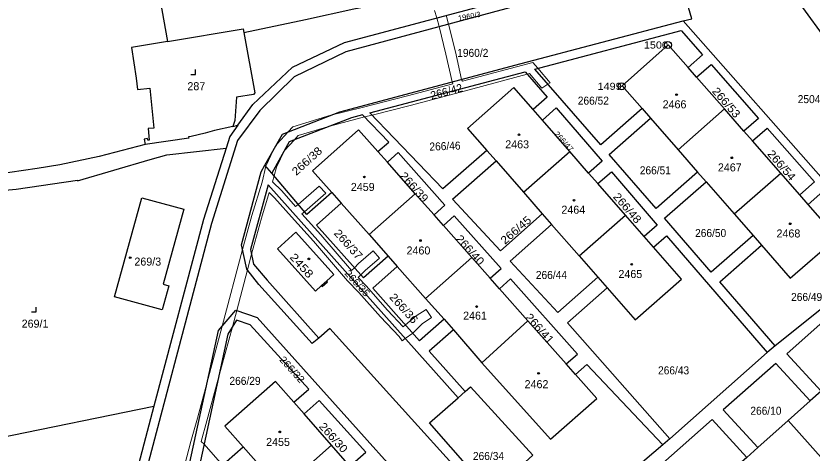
# Model space of a CAD drawing. Extents: x -679733 to -673243, y -1075091 to -1066557.
# Drawn here: x -676434.7 to -676265.6, y -1072010.9 to -1071918.1 of the extents above; entities that cross this region are included whole.
import ezdxf
from ezdxf.enums import TextEntityAlignment as Align

# ---------------------------------------------------------------- set-up
doc = ezdxf.new("R2010")
doc.units = 0
doc.header["$LTSCALE"] = 0.68
for name, color, linetype, lineweight in [('1', 7, 'Continuous', 25), ('13', 7, 'Continuous', 13), ('3', 7, 'Continuous', 25), ('4', 7, 'Continuous', 13), ('5', 7, 'Continuous', 25), ('8', 7, 'Continuous', 25)]:
    doc.layers.add(name, color=color, linetype=linetype, lineweight=lineweight)
doc.layers.add('2', color=7, linetype='Continuous')

msp = doc.modelspace()

# ---------------------------------------------------------------- linework, layer by layer
at = {"layer": '1'}
for p, q in [((-676261.1, -1071955.35), (-676292.99, -1071919.16)), ((-676290.15, -1071931.15), (-676291.95, -1071929.1)), ((-676322.91, -1071940.27), (-676324.88, -1071938.01)), ((-676359.72, -1071964.55), (-676349.94, -1071955.87)), ((-676301.3, -1071964.97), (-676305.24, -1071960.46)), ((-676339.34, -1071997.87), (-676340.79, -1071999.21)), ((-676446.81, -1072009.39), (-676405.43, -1072000.99))]:
    msp.add_line(p, q, dxfattribs=at)
for points in [[(-676408.69, -1071881.95), (-676408.31, -1071891.09), (-676404.9, -1071910.06), (-676402.54, -1071923.54)], [(-676386.32, -1071921.67), (-676373.19, -1071918.89), (-676362.98, -1071916.66), (-676353.15, -1071914.69), (-676349.6, -1071914.02), (-676331.48, -1071909.81), (-676326.61, -1071908.65), (-676299.34, -1071899.31), (-676297.85, -1071896.38)], [(-676387.58, -1071941.35), (-676384.43, -1071936.96), (-676375.96, -1071928.98), (-676364.91, -1071923.77), (-676304.78, -1071907.71), (-676297.93, -1071904.43), (-676296.28, -1071899.99)], [(-676295.13, -1071902.52), (-676296.41, -1071905.95), (-676304.35, -1071909.5), (-676364.66, -1071925.74), (-676375.64, -1071931.09), (-676382.94, -1071938.2), (-676387.67, -1071944.57), (-676393.17, -1071962.19), (-676409.55, -1072024.04), (-676425.12, -1072082.52), (-676427.14, -1072091.8), (-676426.89, -1072108.9), (-676422.15, -1072126.21), (-676412.96, -1072141.55), (-676403.18, -1072152.89), (-676393.86, -1072163.85), (-676389.15, -1072169.1)], [(-676292.99, -1071919.16), (-676291.15, -1071918.74), (-676292.61, -1071913.87), (-676290.05, -1071912.25)], [(-676269.62, -1071912.9), (-676269.95, -1071913.15), (-676260.68, -1071925.96), (-676251.05, -1071935.29), (-676244.6, -1071929.19)], [(-676381.82, -1071949.81), (-676378.12, -1071943.23), (-676365.91, -1071938.49), (-676327.4, -1071928.26), (-676292.99, -1071919.16)], [(-676402.54, -1071923.54), (-676386.46, -1071920.91), (-676386.32, -1071921.67)], [(-676386.32, -1071921.67), (-676384.01, -1071934.48), (-676384.27, -1071934.79), (-676387.85, -1071935.36), (-676387.91, -1071936.4), (-676388.24, -1071940.31), (-676388.68, -1071941.6), (-676387.58, -1071941.35)], [(-676301.74, -1071937.8), (-676310.53, -1071945.49), (-676324.5, -1071929.42), (-676293.47, -1071921.21), (-676288.89, -1071926.41), (-676291.95, -1071929.1)], [(-676402.54, -1071923.54), (-676410.14, -1071924.87), (-676409.17, -1071931.32), (-676408.91, -1071933.75), (-676406.28, -1071933.5), (-676405.46, -1071941.95), (-676406.64, -1071942.06), (-676406.4, -1071944.48), (-676406.69, -1071944.52), (-676406.74, -1071944.17), (-676407.46, -1071944.28), (-676407.29, -1071945.44)], [(-676291.95, -1071929.1), (-676296.21, -1071924.24), (-676305.98, -1071932.95), (-676301.74, -1071937.8), (-676299.95, -1071939.84), (-676294.07, -1071946.56), (-676284.24, -1071937.88), (-676290.15, -1071931.15)], [(-676290.15, -1071931.15), (-676287.09, -1071928.46), (-676277.01, -1071939.9), (-676280.1, -1071942.61)], [(-676334.72, -1071946.67), (-676344.04, -1071954.84), (-676359.52, -1071938.68), (-676326.6, -1071929.97), (-676321.9, -1071935.41), (-676324.88, -1071938.01)], [(-676324.88, -1071938.01), (-676328.95, -1071933.36), (-676338.79, -1071942.02), (-676334.72, -1071946.67), (-676332.75, -1071948.92), (-676326.93, -1071955.55), (-676317.1, -1071946.91), (-676322.91, -1071940.27)], [(-676357.83, -1071946.94), (-676355.54, -1071944.92), (-676361.11, -1071939.11), (-676363.48, -1071939.75), (-676376.69, -1071944.88), (-676380.4, -1071951.48)], [(-676322.91, -1071940.27), (-676319.95, -1071937.68), (-676310.2, -1071948.96), (-676313.09, -1071951.49)], [(-676294.07, -1071946.56), (-676289.95, -1071951.28), (-676288.16, -1071953.33), (-676282.18, -1071960.17), (-676272.29, -1071951.51), (-676278.3, -1071944.66), (-676280.1, -1071942.61), (-676284.24, -1071937.88)], [(-676289.95, -1071951.28), (-676298.78, -1071959.01), (-676308.75, -1071947.54), (-676299.95, -1071939.84)], [(-676388.68, -1071941.6), (-676392.51, -1071942.48), (-676394.55, -1071943.02), (-676397.5, -1071943.7), (-676398.07, -1071943.8), (-676398.02, -1071944.08), (-676407.29, -1071945.44)], [(-676387.58, -1071941.35), (-676389.28, -1071943.71), (-676390.08, -1071946.22)], [(-676357.83, -1071946.94), (-676361.97, -1071942.33), (-676371.74, -1071951), (-676367.63, -1071955.64), (-676365.63, -1071957.88), (-676359.72, -1071964.55)], [(-676278.3, -1071944.66), (-676275.2, -1071941.94), (-676265.12, -1071953.38), (-676268.24, -1071956.12)], [(-676407.29, -1071945.44), (-676417.02, -1071948.01), (-676425.37, -1071949.72), (-676430.22, -1071950.53), (-676436.03, -1071951.34), (-676444.6, -1071952.15), (-676451.96, -1071952.38), (-676459.08, -1071952.16), (-676466.06, -1071951.13)], [(-676446.81, -1072009.39), (-676450.6, -1071997.32), (-676455.21, -1071989.93), (-676455.68, -1071988.73), (-676463.71, -1071957.6), (-676434.64, -1071954.92), (-676421.63, -1071953.01), (-676421.61, -1071953.11), (-676406.22, -1071948.58), (-676402.7, -1071947.59), (-676390.08, -1071946.22)], [(-676390.08, -1071946.22), (-676394.9, -1071961.33), (-676405.43, -1072000.99), (-676410.13, -1072018.72)], [(-676349.94, -1071955.87), (-676355.83, -1071949.19), (-676357.83, -1071946.94)], [(-676345.91, -1071960.37), (-676343.6, -1071958.32), (-676353.55, -1071947.16), (-676355.83, -1071949.19)], [(-676311.12, -1071953.74), (-676313.09, -1071951.49), (-676317.1, -1071946.91)], [(-676322.93, -1071960.12), (-676331.81, -1071968), (-676342.01, -1071957.03), (-676332.75, -1071948.92)], [(-676370.36, -1071986.54), (-676371.83, -1071987.69), (-676383.12, -1071975.15), (-676385.67, -1071971.87), (-676386.84, -1071966.72), (-676382.61, -1071951.21), (-676381.82, -1071949.81)], [(-676367.63, -1071955.64), (-676372.9, -1071960.32), (-676380.4, -1071951.48), (-676381.82, -1071949.81)], [(-676311.12, -1071953.74), (-676308.25, -1071951.23), (-676298.5, -1071962.52), (-676301.3, -1071964.97)], [(-676276.37, -1071966.81), (-676270.27, -1071973.78), (-676260.32, -1071965.15), (-676266.45, -1071958.17), (-676268.24, -1071956.12), (-676272.29, -1071951.51)], [(-676340.79, -1071999.21), (-676381.18, -1071953.99), (-676384.92, -1071967.69), (-676384.28, -1071970.84), (-676381.34, -1071974.24), (-676370.36, -1071986.54)], [(-676326.93, -1071955.55), (-676322.93, -1071960.12), (-676320.95, -1071962.38), (-676315.07, -1071969.09), (-676305.24, -1071960.46), (-676311.12, -1071953.74)], [(-676278.15, -1071964.77), (-676287.04, -1071972.53), (-676297, -1071961.06), (-676288.16, -1071953.33)], [(-676347.71, -1071978.09), (-676337.92, -1071969.41), (-676343.92, -1071962.62), (-676345.91, -1071960.37), (-676349.94, -1071955.87)], [(-676266.45, -1071958.17), (-676263.32, -1071955.43), (-676262.41, -1071956.46), (-676261.1, -1071955.35)], [(-676355.68, -1071969.11), (-676360.9, -1071973.74), (-676370.9, -1071962.56), (-676365.63, -1071957.88)], [(-676334, -1071973.8), (-676331.66, -1071971.72), (-676341.61, -1071960.56), (-676343.92, -1071962.62)], [(-676282.18, -1071960.17), (-676278.15, -1071964.77), (-676276.37, -1071966.81)], [(-676311.13, -1071973.59), (-676319.63, -1071981.09), (-676329.78, -1071970.18), (-676320.95, -1071962.38)], [(-676359.72, -1071964.55), (-676355.68, -1071969.11), (-676353.72, -1071971.31), (-676347.71, -1071978.09)], [(-676309.16, -1071975.83), (-676303.21, -1071982.62), (-676293.39, -1071974.01), (-676299.33, -1071967.22), (-676301.3, -1071964.97)], [(-676299.33, -1071967.22), (-676296.55, -1071964.78), (-676275.14, -1071989.58)], [(-676273.47, -1071988.14), (-676285.25, -1071974.58), (-676276.37, -1071966.81)], [(-676335.74, -1071991.74), (-676325.97, -1071982.85), (-676332.01, -1071976.04), (-676334, -1071973.8), (-676337.92, -1071969.41)], [(-676315.07, -1071969.09), (-676311.13, -1071973.59), (-676309.16, -1071975.83)], [(-676343.8, -1071982.49), (-676348.98, -1071987.09), (-676358.94, -1071975.94), (-676353.72, -1071971.31)], [(-676317.84, -1071992.01), (-676315.45, -1071989.9), (-676329.66, -1071973.96), (-676332.01, -1071976.04)], [(-676295.84, -1072007.9), (-676317.6, -1071983.28), (-676309.16, -1071975.83)], [(-676253.86, -1071979.52), (-676258.66, -1071976.34), (-676273.47, -1071988.14)], [(-676347.71, -1071978.09), (-676343.8, -1071982.49), (-676341.81, -1071984.75), (-676335.74, -1071991.74)], [(-676254.89, -1071980.47), (-676258.79, -1071979.07), (-676271, -1071989.84), (-676263.67, -1071997.76)], [(-676390.45, -1072017.54), (-676393.75, -1072020.45), (-676398.47, -1072016.2), (-676391.69, -1071984.93), (-676388.01, -1071980.59), (-676383.5, -1071982.16), (-676332.46, -1072039.02)], [(-676375.71, -1072000.14), (-676372.54, -1071997.35), (-676384.98, -1071983.69), (-676387.9, -1071982.71), (-676389.69, -1071985.66), (-676395.95, -1072014.53), (-676393.53, -1072015.85), (-676386.44, -1072009.61)], [(-676335.74, -1071991.74), (-676321.17, -1072008), (-676311.37, -1071999.31), (-676315.85, -1071994.26), (-676317.84, -1071992.01), (-676325.97, -1071982.85)], [(-676324.68, -1072032.42), (-676368.06, -1071984.49), (-676370.36, -1071986.54)], [(-676341.81, -1071984.75), (-676346.97, -1071989.33), (-676339.34, -1071997.87)], [(-676273.47, -1071988.14), (-676275.14, -1071989.58), (-676295.84, -1072007.9), (-676297.3, -1072009.2), (-676324.68, -1072032.42)], [(-676297.3, -1072009.2), (-676313.46, -1071992.13), (-676315.85, -1071994.26)], [(-676266.03, -1071999.86), (-676273.36, -1071991.92), (-676284.49, -1072001.73), (-676277.17, -1072009.77)], [(-676375.71, -1072000.14), (-676379.61, -1071995.72), (-676390.34, -1072005.18), (-676386.44, -1072009.61)], [(-676339.34, -1071997.87), (-676338.18, -1071996.86), (-676324.95, -1072011.36), (-676333.76, -1072019.47), (-676346.85, -1072004.49), (-676340.79, -1071999.21)], [(-676263.67, -1071997.76), (-676266.03, -1071999.86), (-676270.68, -1072004)], [(-676363.77, -1072013.69), (-676360.39, -1072010.7), (-676370.32, -1071999.8), (-676373.53, -1072002.62)], [(-676386.44, -1072009.61), (-676384.26, -1072012.08), (-676378.4, -1072018.73), (-676367.67, -1072009.27), (-676373.53, -1072002.62), (-676375.71, -1072000.14)], [(-676279.52, -1072011.86), (-676286.84, -1072003.8), (-676297.97, -1072013.61), (-676290.66, -1072021.77)], [(-676270.68, -1072004), (-676277.17, -1072009.77), (-676279.52, -1072011.86), (-676284.18, -1072016)], [(-676267.4, -1072020.94), (-676260.82, -1072015.12), (-676270.68, -1072004)], [(-676366.44, -1072032.28), (-676355.71, -1072022.83), (-676361.59, -1072016.16), (-676363.77, -1072013.69), (-676367.67, -1072009.27)]]:
    msp.add_lwpolyline(points, dxfattribs=at)
for points in [[(-676403.64, -1071980.54), (-676413.76, -1071977.77), (-676407.99, -1071956.72), (-676399.05, -1071959.17), (-676403.42, -1071975.1), (-676402.24, -1071975.43)], [(-676375.28, -1071964.07), (-676379.17, -1071967.58), (-676371.11, -1071976.55), (-676369.8, -1071975.37), (-676369.65, -1071975.54), (-676368.56, -1071974.58), (-676368.72, -1071974.4), (-676367.21, -1071973.05)]]:
    msp.add_lwpolyline(points, close=True, dxfattribs=at)
at = {"layer": '13'}
for points in [[(-676345.79, -1071917.01), (-676345.31, -1071918.54), (-676344.85, -1071920.4), (-676343.39, -1071926.26), (-676342.06, -1071932.15), (-676341.96, -1071932.58), (-676351.53, -1071935.13), (-676361.2, -1071937.55), (-676367.82, -1071939.23), (-676375.9, -1071941.68), (-676376.91, -1071942.76), (-676379.27, -1071945.28), (-676379.98, -1071946.54), (-676381.62, -1071950.04), (-676382.44, -1071953.41), (-676384.61, -1071960.5), (-676386.61, -1071967.72), (-676390.88, -1071983.98), (-676393.89, -1071995.07), (-676396.18, -1072003.51), (-676397.57, -1072008.47), (-676402.32, -1072026.65)], [(-676390.85, -1072013.49), (-676394.76, -1072009.02), (-676395.39, -1072008.47), (-676394.16, -1072004.07), (-676391.81, -1071995.42), (-676388.74, -1071984.1), (-676387.81, -1071980.66), (-676385.56, -1071972.01), (-676384.71, -1071968.74), (-676382.59, -1071961.08), (-676380.9, -1071955.65), (-676379.77, -1071956.72), (-676376.2, -1071960.75), (-676371.55, -1071965.98), (-676364.29, -1071974.38), (-676361.87, -1071976.86), (-676357.31, -1071982), (-676353.36, -1071986.18), (-676352.7, -1071987.12), (-676352.02, -1071986.63), (-676350.42, -1071985.48), (-676348.46, -1071983.47), (-676346.46, -1071982.13), (-676347.6, -1071980.43), (-676349.68, -1071981.83), (-676351.99, -1071983.72), (-676352.46, -1071984.11), (-676355.77, -1071980.6), (-676360.35, -1071975.46), (-676362.03, -1071973.69), (-676361.46, -1071973.11), (-676360.55, -1071972.17), (-676357.53, -1071969.56), (-676358.87, -1071968.02), (-676361.95, -1071970.67), (-676362.83, -1071971.58), (-676363.43, -1071972.2), (-676369.99, -1071964.6), (-676373.97, -1071960.13), (-676373.43, -1071959.7), (-676368.93, -1071955.75), (-676370.31, -1071954.25), (-676374.75, -1071958.14), (-676375.33, -1071958.6), (-676378.27, -1071955.28), (-676380.25, -1071953.38), (-676379.9, -1071952.07), (-676379.4, -1071950.25), (-676377.69, -1071946.67), (-676375.65, -1071944.48), (-676374.76, -1071943.52), (-676368.08, -1071941.54), (-676360.66, -1071939.58), (-676359.04, -1071939.18), (-676351.01, -1071937.17), (-676340.28, -1071934.3), (-676326.14, -1071930.5), (-676325.63, -1071930.36), (-676323.02, -1071933.49), (-676321.72, -1071932.62), (-676321.28, -1071932.33), (-676323.87, -1071929.25), (-676324.93, -1071928), (-676339.87, -1071932.02), (-676340.06, -1071931.62), (-676341.39, -1071925.78), (-676342.86, -1071919.87), (-676343.32, -1071918)]]:
    msp.add_lwpolyline(points, dxfattribs=at)
at = {"layer": '3'}
for points in [[(-676397.591, -1071930.54), (-676396.59, -1071930.54), (-676396.59, -1071929.54)], [(-676431.401, -1071980.96), (-676430.4, -1071980.96), (-676430.4, -1071979.96)]]:
    msp.add_lwpolyline(points, dxfattribs=at)
at = {"layer": '4'}
msp.add_line((-676369.8, -1071975.37), (-676368.72, -1071974.4), dxfattribs=at)
at = {"layer": '5'}
for centre in [(-676294.4168, -1071934.8392), (-676327.8768, -1071943.3692), (-676282.6768, -1071948.2492), (-676360.7168, -1071952.3192), (-676316.1868, -1071957.2592), (-676270.2768, -1071962.2592), (-676348.7968, -1071965.8092), (-676410.4368, -1071969.4392), (-676372.5068, -1071969.6992), (-676303.9468, -1071970.8492), (-676336.8768, -1071979.8192), (-676323.7268, -1071994.0092), (-676378.6768, -1072006.4292)]:
    msp.add_circle(centre, 0.175, dxfattribs=at)
at = {"layer": '8'}
for centre, radius in [((-676296.24, -1071924.3098), 0.75), ((-676296.24, -1071924.3098), 0.03), ((-676306.07, -1071933.0798), 0.75), ((-676306.07, -1071933.0798), 0.03)]:
    msp.add_circle(centre, radius, dxfattribs=at)

# ---------------------------------------------------------------- texts
at = {"layer": '2'}
msp.add_text('1960/3', height=1.14, rotation=11, dxfattribs=at).set_placement((-676340.681, -1071919.219))
at = {"layer": '2', "width": 0.95}
for s, p in [('1960/2', (-676337.689, -1071926.83)), ('2504/9', (-676265.379, -1071936.65)), ('266/51', (-676298.919, -1071951.759)), ('266/50', (-676287.179, -1071965.07)), ('266/44', (-676320.989, -1071973.97)), ('266/49', (-676266.789, -1071978.64)), ('266/29', (-676386.059, -1071996.45)), ('266/10', (-676275.439, -1072002.79))]:
    msp.add_text(s, height=1.7, dxfattribs=at).set_placement(p, align=Align.CENTER)
at = {"layer": '2'}
for s, p in [('287', (-676398.3, -1071933.9)), ('269/1', (-676433.5, -1071984.31))]:
    msp.add_text(s, height=1.7, dxfattribs=at).set_placement(p)
msp.add_text('266/42', height=1.7, rotation=15, dxfattribs=at).set_placement((-676343.0635, -1071935.0212), align=Align.CENTER)
for s, height, rotation, width, p in [('266/53', 1.7, 311, 1.1, (-676284.4879, -1071937.0789)), ('266/38', 1.7, 42, 1.1, (-676372.3413, -1071949.5697)), ('266/54', 1.7, 311, 1.1, (-676272.7479, -1071950.3889)), ('266/39', 1.7, 312, 1.1, (-676350.7597, -1071955.0377)), ('266/48', 1.7, 311, 1.1, (-676305.5079, -1071959.4689)), ('266/37', 1.7, 312, 1.1, (-676364.7497, -1071967.1977)), ('266/40', 1.7, 312, 1.1, (-676338.8897, -1071968.3877)), ('2458', 1.7, 312, 1.2, (-676374.6601, -1071971.6972)), ('266/35', 1.5, 312, 1.1, (-676362.7661, -1071975.3762)), ('266/36', 1.7, 312, 1.1, (-676352.9697, -1071980.7777)), ('266/41', 1.7, 312, 1.1, (-676324.0997, -1071985.0477)), ('266/32', 1.5, 312, 1.1, (-676376.6161, -1071993.6962)), ('266/30', 1.7, 312, 1.1, (-676367.9097, -1072008.2077))]:
    msp.add_text(s, height=height, rotation=rotation, dxfattribs=dict(at, width=width)).set_placement(p, align=Align.CENTER)
at = {"layer": '2', "width": 0.95}
for s, p in [('266/52', (-676315.39, -1071936.97)), ('266/43', (-676298.35, -1071994.22)), ('266/34', (-676337.66, -1072012.39))]:
    msp.add_text(s, height=1.7, dxfattribs=at).set_placement(p)
at = {"layer": '2'}
for s, p in [('2466', (-676294.85, -1071937.749)), ('2463', (-676328.27, -1071946.239)), ('2467', (-676283.11, -1071951.14)), ('2459', (-676361.06, -1071955.29)), ('2464', (-676316.35, -1071960.12)), ('2468', (-676270.66, -1071965.16)), ('2460', (-676349.23, -1071968.769)), ('269/3', (-676406.71, -1071971.13)), ('2465', (-676304.23, -1071973.769)), ('2461', (-676337.22, -1071982.61)), ('2462', (-676324.16, -1071997.15)), ('2455', (-676379.05, -1072009.41))]:
    msp.add_text(s, height=1.7, dxfattribs=at).set_placement(p, align=Align.CENTER)
for s, height, rotation, width, p in [('266/47', 1.14, 312, 1.1, (-676320.463, -1071943.261)), ('266/46', 1.7, 2, 0.95, (-676346.87, -1071946.729)), ('266/45', 1.7, 41, 1.1, (-676330.862, -1071966.741))]:
    msp.add_text(s, height=height, rotation=rotation, dxfattribs=dict(at, width=width)).set_placement(p)
at = {"layer": '8', "width": 1.15}
for s, p in [('1500', (-676296.239, -1071925.06)), ('1499', (-676306.069, -1071933.83))]:
    msp.add_text(s, height=1.5, dxfattribs=at).set_placement(p, align=Align.RIGHT)

doc.saveas('drawing.dxf')
